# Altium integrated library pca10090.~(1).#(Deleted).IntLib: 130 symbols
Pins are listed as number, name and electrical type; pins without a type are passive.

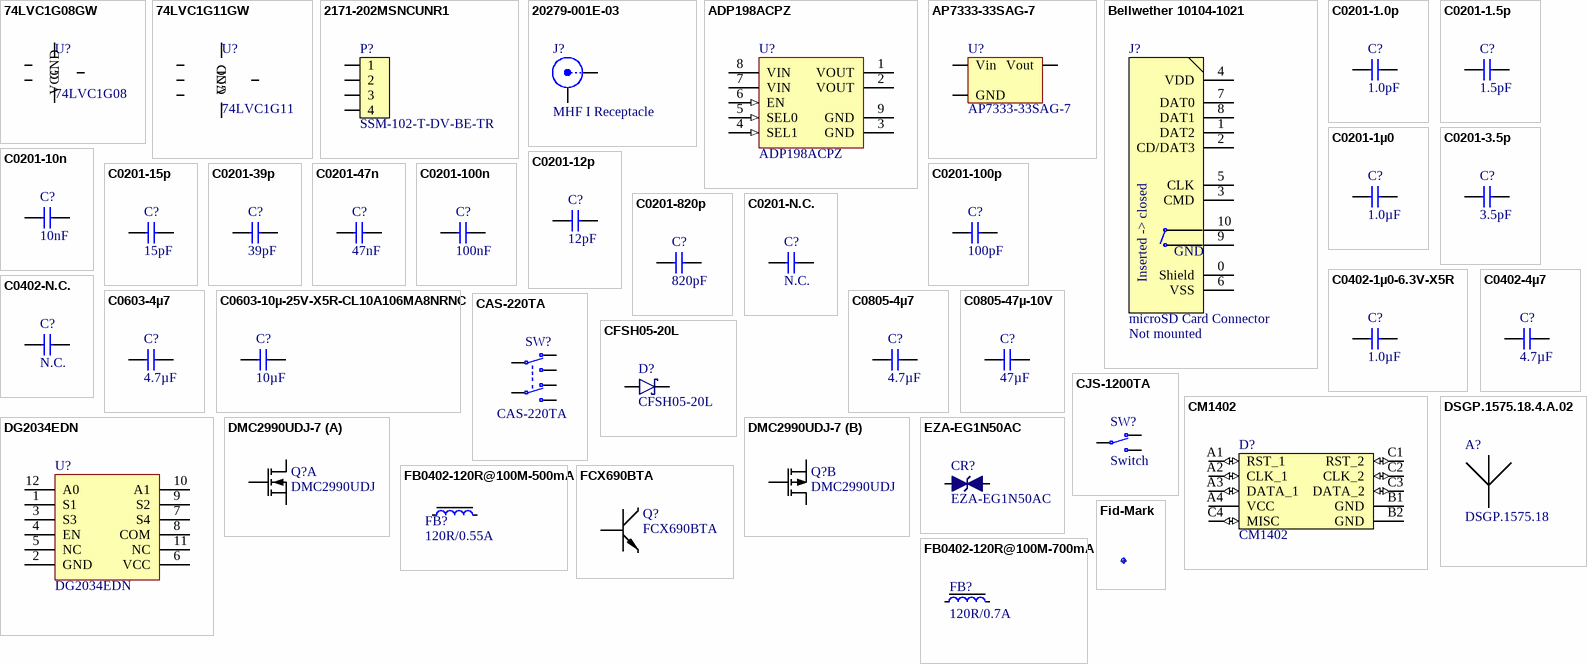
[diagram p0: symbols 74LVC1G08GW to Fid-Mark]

## 74LVC1G08GW
designator U?, comment 74LVC1G08
Single 2-Input AND Gate; Part Number: 74LVC1G08GW; Manufacturer: NXP Semiconductors; Part number IPS: 00000009992; Part number Norautron: N.A.; Artikkelnr Noca: 15049058; Pad Count: 5
footprint SOT65P210X100-5N
pins: 1 A, 2 B, 3 GND (power), 4 Y, 5 VCC (power)

## 74LVC1G11GW
designator U?, comment 74LVC1G11
Single 3-input AND gate; Part Number: 74LVC1G11GW; Manufacturer: NXP Semiconductors; Part number IPS: 00000001430; Part number Norautron: N.A.; Artikkelnr Noca: 15079348; Pad Count: 6
footprint SOT65P210X100-6N
pins: 1 A, 2 GND (power), 3 B, 4 Y, 5 VCC (power), 6 C

## 2171-202MSNCUNR1
designator P?, comment SSM-102-T-DV-BE-TR
.025 SOCKET STRIPS; Part Number: 2171-202MSNCUNR1; Manufacturer: W-CON; Part number IPS: 00000001417; Note: N.A.; Pad Count: 4
footprint SSM-102-T-DV-BE-TR
pins: 1, 2, 3, 4

## 20279-001E-03
designator J?, comment MHF I Receptacle
Ultraminiature Coaxial Connector, 50 Ohm, SMD; Part Number: 20279-001E-03; Manufacturer: Wellshow; Part number IPS: 00000004436; Note: N.A.; Pad Count: 3
footprint COAXIAL RF U.FL-R-SMT-1
pins: 1 X, 2 Y

## ADP198ACPZ
designator U?
Logic Controlled, 1 A, High-Side Load Switch with Reverse Current Blocking; Manufacturer: Analog Devices; Part number IPS: 00000002999; Note: N.A.; Pad Count: 8
footprint UFDFN50P200X200X60_HS-9N
pins: 1 VOUT (power), 2 VOUT (power), 3 GND (power), 4 SEL1 (in), 5 SEL0 (in), 6 EN (in), 7 VIN (power), 8 VIN (power), 9 GND (power)

## AP7333-33SAG-7
designator U?
300mA, Low Quiescent Current, Fast Transient Low Dropout Linear Regulator; Manufacturer: Diodes Incorporated; Part number IPS: 00000001673; Note: N.A.; Artikkelnr Noca: 17039216; Pad Count: 3
footprint SOT-23A
pins: 1 Vin, 2 Vout, 3 GND

## Bellwether 10104-1021
designator J?, comment microSD Card Connector  Assembly: Not mounted
1.10mm Pitch microSD Memory Card Connector, Reverse Mount Surface Mount, Push-Push Type; Part Number: Bellwether 10104-1021; Manufacturer: Bellwether; Manufacturer Part Number: 10104-1021; Note: N.A.; Pad Count: 14
footprint Molex_502774-0891
pins: 0 Shield, 1 DAT2, 2 CD/DAT3, 3 CMD, 4 VDD (power), 5 CLK, 6 VSS (power), 7 DAT0, 8 DAT1, 9, 10

## C0201-1.0p
designator C?, comment 1.0pF
Capacitor, NP0, ±0.05pF, 50V; Part Number: C0201-1.0p; Manufacturer: N.A.; Part number IPS: 00000001247; Pad Count: 2
footprint CAPC0603X03L_C
pins: 1, 2

## C0201-1.5p
designator C?, comment 1.5pF
Capacitor, NP0, ±0.1pF; Part Number: C0201-1.5p; Manufacturer: N.A.; Part number IPS: 00000007107; Note: 50V; Pad Count: 2
footprint CAPC0603X03L_C
pins: 1, 2

## C0201-1µ0
designator C?, comment 1.0µF
Capacitor, X5R, ±10%; Part Number: C0201-1µ0; Manufacturer: N.A.; Part number IPS: 00000001723; Note: 10V; Pad Count: 2
footprint CAPC0603X03L_C
pins: 1, 2

## C0201-3.5p
designator C?, comment 3.5pF
Capacitor, NP0, ±0.1pF, 25V; Part Number: C0201-3.5p; Manufacturer: Murata; Manufacturer Part Number: GJM0335C1H3R5BB01E; Part number IPS: 00000001469; Artikkelnr Noca: N.A.; Pad Count: 2
footprint CAPC0603X03L_C
pins: 1, 2

## C0201-10n
designator C?, comment 10nF
Capacitor, X7R, ±10%; Part Number: C0201-10n; Manufacturer: N.A.; Part number IPS: 00000003480; Note: 10V; Pad Count: 2
footprint CAPC0603X03L_C
pins: 1, 2

## C0201-12p
designator C?, comment 12pF
Capacitor, NP0, ±2%; Part Number: C0201-12p; Manufacturer: N.A.; Part number IPS: 00000007848; Note: 25V; Pad Count: 2
footprint CAPC0603X03L_C
pins: 1, 2

## C0201-15p
designator C?, comment 15pF
Capacitor, NP0, ±5%, 25V; Part Number: C0201-15p; Manufacturer: Murata; Manufacturer Part Number: GRM0335C1E150JD03D; Part number IPS: 00000003193; Artikkelnr Noca: N.A.; Pad Count: 2
footprint CAPC0603X03L_C
pins: 1, 2

## C0201-39p
designator C?, comment 39pF
Capacitor, NP0, ±1%, 25V; Part Number: C0201-39p; Manufacturer: Murata; Manufacturer Part Number: GRM0335C1E390FA01; Part number IPS: 00000001668; Artikkelnr Noca: N.A.; Pad Count: 2
footprint CAPC0603X03L_C
pins: 1, 2

## C0201-47n
designator C?, comment 47nF
Capacitor, X5R, ±10%; Part Number: C0201-47n; Manufacturer: N.A.; Part number IPS: 00000001250; Note: 10V; Pad Count: 2
footprint CAPC0603X03L_C
pins: 1, 2

## C0201-100n
designator C?, comment 100nF
Capacitor, X5R, ±10%; Part Number: C0201-100n; Manufacturer: N.A.; Part number IPS: 00000001248, 00000002505; Note: 16V; Pad Count: 2
footprint CAPC0603X03L_C
pins: 1, 2

## C0201-100p
designator C?, comment 100pF
Capacitor, NP0, ±2%, 25V; Part Number: C0201-100p; Manufacturer: Murata; Manufacturer Part Number: GRM0335C1E101GA01; Part number IPS: 00000007853; Artikkelnr Noca: N.A.; Pad Count: 2
footprint CAPC0603X03L_C
pins: 1, 2

## C0201-820p
designator C?, comment 820pF
Capacitor, X7R, ±10%; Part Number: C0201-820p; Manufacturer: N.A.; Part number IPS: 00000001249; Note: 25V; Pad Count: 2
footprint CAPC0603X03L_C
pins: 1, 2

## C0201-N.C.
designator C?, comment N.C.
Not mounted; Part Number: C0201-N.C.; Manufacturer: N.A.; Note: Chip Cap; Assembly: Not mounted; Pad Count: 2
footprint CAPC0603X03L_C_NC
pins: 1, 2

## C0402-1µ0-6.3V-X5R
designator C?, comment 1.0µF
Capacitor, X5R, ±5%, 6.3V; Part Number: C0402-1µ0-6.3V-X5R; Manufacturer: N.A.; Part number IPS: 00000007786, 00000003457; Artikkelnr Noca: 20039235; Pad Count: 2
footprint CAPC1005X04L
pins: 1, 2

## C0402-4µ7
designator C?, comment 4.7µF
Capacitor, X5R, ±20%; Part Number: C0402-4µ7; Manufacturer: N.A.; Part number IPS: 00000001251, 00000007165; Note: 10V; Artikkelnr Noca: 20039482; Pad Count: 2
footprint CAPC1005X04L
pins: 1, 2

## C0402-N.C.
designator C?, comment N.C.
Not mounted; Part Number: C0402-N.C.; Manufacturer: N.A.; Assembly: Not mounted; Note: Chip Cap; Pad Count: 2
footprint CAPC1005X04L_NC
pins: 1, 2

## C0603-4µ7
designator C?, comment 4.7µF
Capacitor, X5R, ±10%; Part Number: C0603-4µ7; Manufacturer: N.A.; Part number IPS: 00000007783; Note: 6.3V; Artikkelnr Noca: 20069060; Pad Count: 2
footprint CAPC1608X06L
pins: 1, 2

## C0603-10µ-25V-X5R-CL10A106MA8NRNC
designator C?, comment 10µF
Capacitor, X5R, ±20%, 25V; Part Number: C0603-10µ-25V-X5R-CL10A106MA8NRNC; Manufacturer: Samsung Electro-Mechanics America; Manufacturer Part Number: CL10A106MA8NRNC; Part number IPS: 00000009948; Part number Norautron: N.A.; Artikkelnr Noca: 20039436; Pad Count: 2
footprint CAPC1608X06L
pins: 1, 2

## C0805-4µ7
designator C?, comment 4.7µF
Capacitor, X5R, ±10%, 16V; Part Number: C0805-4µ7; Manufacturer: N.A.; Part number IPS: 00000006289; Artikkelnr Noca: 20039266; Pad Count: 2
footprint CAPC2012X11L
pins: 1, 2

## C0805-47µ-10V
designator C?, comment 47µF
Capacitor, X5R, ±20%, 10V; Part Number: C0805-47µ-10V; Manufacturer: Murata; Manufacturer Part Number: GRM21BR61A476ME15; Part number IPS: 00000004759; Artikkelnr Noca: N.A.; Pad Count: 2
footprint CAPC2012X11L
pins: 1, 2

## CAS-220TA
designator SW?
Slide Switch DPDT J Hook; Manufacturer: Copal Electronics Inc; Part number IPS: 00000009983; Note: N.A.; Artikkelnr Noca: 50019042; Pad Count: 6
footprint CAS-220TA
pins: 1 N.O-1, 2 COM-1, 3 N.C-1, 4 N.O-2, 5 COM-2, 6 N.C-2

## CFSH05-20L
designator D?
DIODE SCHOTTKY 20V 500MA SOD882; Manufacturer: Central Semiconductor Corp.; Part number IPS: 00000002493; Note: N.A.; Pad Count: 2
footprint SODFL35X40-2N
pins: 1 A, 3 C

## CJS-1200TA
designator SW?, comment Switch
SMD slide Switch (ON-ON); Part Number: CJS-1200TA; Manufacturer: Copal Electronics Inc; Part number IPS: 00000009982; Note: N.A.; Artikkelnr Noca: 50019068; Pad Count: 3
footprint CJS-120xA
pins: 1 N.C, 2 COM, 3 N.O

## CM1402
designator D?
EMI Network Filter Arrays SIM CARD EMI FILTER WITH ESD PROTECTION; Manufacturer: ON Semiconductor; Manufacturer Part Number: CM1402-03CP; Part number IPS: 00000009949; Note: N.A.; Pad Count: 10
footprint CM1402
pins: A1 RST_1 (io), A2 CLK_1 (io), A3 DATA_1 (io), A4 VCC (power), B1 GND (power), B2 GND (power), C1 RST_2 (io), C2 CLK_2 (io), C3 DATA_2 (io), C4 MISC (io)

## DG2034EDN
designator U?
POWER DOWN FAULT PROTECTED,1.8VT; Manufacturer: Vishay; Manufacturer Part Number: DG2034EDN-T1-GE4; Part number IPS: 00000001429; Note: N.A.; Pad Count: 12
footprint DG2034EDN
pins: 1 S1, 2 GND, 3 S3 (power), 4 EN, 5 NC, 6 VCC (power), 7 S4, 8 COM, 9 S2, 10 A1, 11 NC, 12 A0

## DMC2990UDJ-7
designator Q?, comment DMC2990UDJ
MOSFET, Dual N and P-Channel, 20V, 450mA/310mA, 990mOhm, 350mW; Part Number: DMC2990UDJ-7; Manufacturer: Diodes Incorporated; Part number IPS: 00000004489; Note: N.A.; Pad Count: 6
footprint SOTFL35P100X50-6N
part A pins: 1 S1, 2 G1, 6 D1
part B pins: 3 D2, 4 S2, 5 G2

## DSGP.1575.18.4.A.02
designator A?, comment DSGP.1575.18
18 x 18 mm Low Profile GPS L1 / GALILEO E1 Passive Patch Antenna; Part Number: DSGP.1575.18.4.A.02; Manufacturer: Taoglas; Part number IPS: 00000004435; Note: N.A.; Pad Count: 2
footprint DSGP.1575.18
pins: 1, 2 GND (power) hidden to GND

## EZA-EG1N50AC
designator CR?
ESD Suppressor, 30V, 0.04pF; Manufacturer: Panasonic; Part number IPS: 00000004437; Note: N.A.; Pad Count: 2
footprint RESC0603X03L_C
pins: 1, 2

## FB0402-120R@100M-500mA
designator FB?, comment 120R/0.55A
Ferrite Bead, 120 Ohm @ 100MHz, 500mA, 250 mOhm Max; Part Number: FB0402-120R@100M-500mA; Manufacturer: Murata; Manufacturer Part Number: BLM15AG121SN1D; Part number IPS: 00000009954; Part number Norautron: N.A.; Note: Chip EMIFIL Inductor Type Chip Ferrite Bead; Artikkelnr Noca: 33029317; Pad Count: 2
footprint INDC1005X04L
pins: 1, 2

## FB0402-120R@100M-700mA
designator FB?, comment 120R/0.7A
Ferrite Bead, 120 Ohm @ 100MHz, 700mA, 130 mOhm Max; Part Number: FB0402-120R@100M-700mA; Manufacturer: Murata; Manufacturer Part Number: BLM15AX121SN1; Part number IPS: 00000004487; Note: N.A.; Pad Count: 2
footprint INDC1005X04L
pins: 1, 2

## FCX690BTA
designator Q?
45V NPN high gain power transistor; Manufacturer: Diodes Incorporated; Part number IPS: 00000009974; Note: N.A.; Artikkelnr Noca: 35010019; Pad Count: 3
footprint SOT89-150P409X160-3N
pins: 1 B, 2 C (power), 3 E (power)

## Fid-Mark
designator Fid?, comment Fiducial mark  (value not drawn)
Part Number: Fid-Mark; Manufacturer: N.A.; Value: N.A.; Pad Count: 1
footprint Fiducial

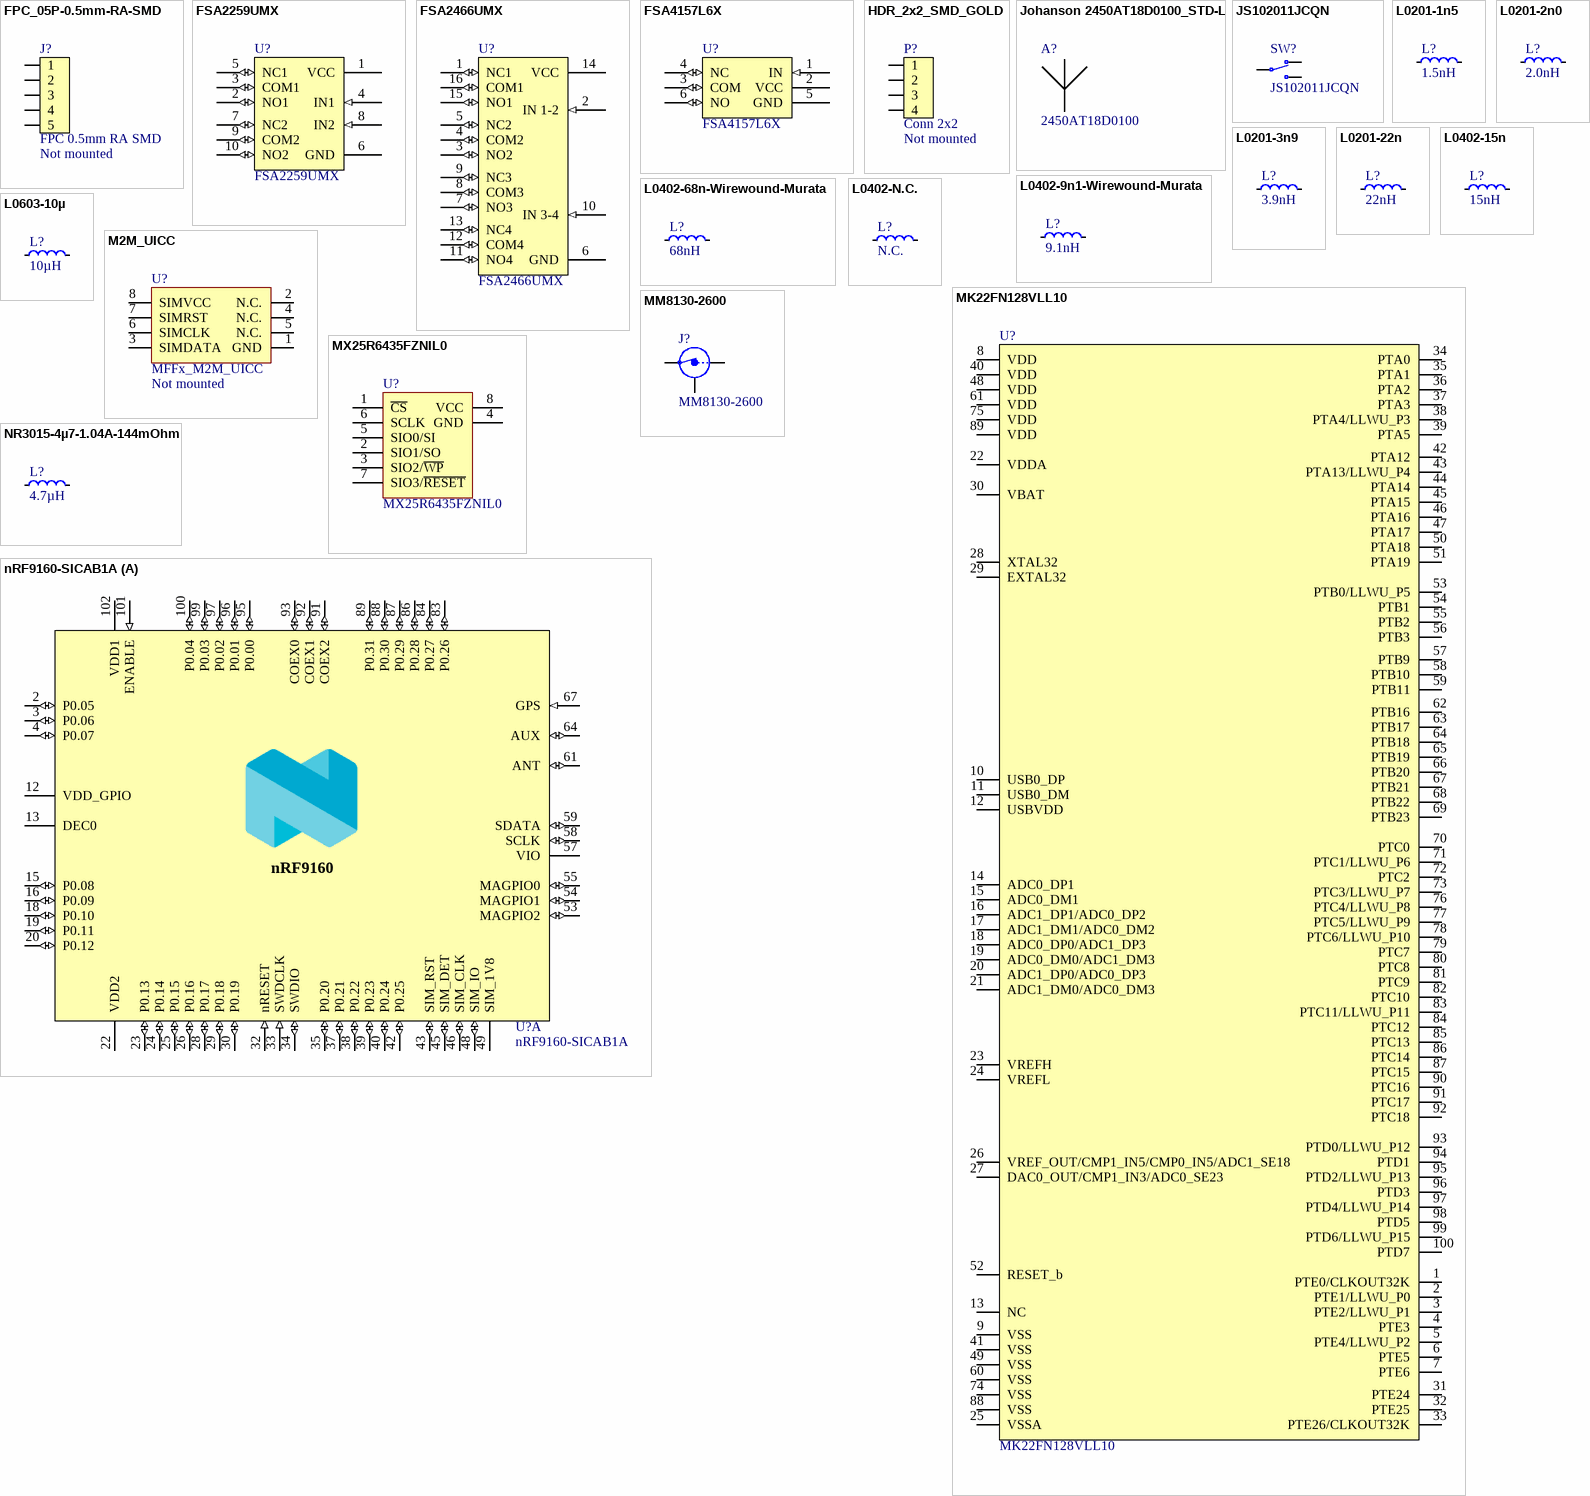
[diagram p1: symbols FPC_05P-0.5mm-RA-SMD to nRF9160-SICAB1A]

## FPC_05P-0.5mm-RA-SMD
designator J?, comment FPC 0.5mm RA SMD  Assembly: Not mounted
0.5mm FPC, 5P,Right Angle SMT,Double Contact,H=1.2mm,White, Tin plated; Part Number: FPC_05P-0.5mm-RA-SMD; Manufacturer: W-CON; Manufacturer Part Number: 5141-05RZDNWR02; Part number IPS: 00000007792; Note: N.A.; Artikkelnr Noca: 55010020; Pad Count: 7
footprint FPC_05P-0.5mm-RA-SMD
pins: 1, 2, 3, 4, 5

## FSA2259UMX
designator U?
Low-Voltage, Dual-SPDT analog Switch; Manufacturer: ON Semiconductor; Part number IPS: 00000002998; Note: N.A.; Pad Count: 10
footprint UFQFN40P140X180X55-10N
pins: 1 VCC (power), 2 NO1 (io), 3 COM1 (io), 4 IN1 (in), 5 NC1 (io), 6 GND (power), 7 NC2 (io), 8 IN2 (in), 9 COM2 (io), 10 NO2 (io)

## FSA2466UMX
designator U?
Data / Audio Low-Voltage Dual DPDT Analog Switch; Manufacturer: ON Semiconductor; Part number IPS: 00000009986; Note: N.A.; Artikkelnr Noca: 15070069; Pad Count: 16
footprint XQFN40P180X260X50-16N
pins: 1 NC1 (io), 2 IN 1-2 (in), 3 NO2 (io), 4 COM2 (io), 5 NC2 (io), 6 GND (power), 7 NO3 (io), 8 COM3 (io), 9 NC3 (io), 10 IN 3-4 (in), 11 NO4 (io), 12 COM4 (io), 13 NC4 (io), 14 VCC (power), 15 NO1 (io), 16 COM1 (io)
1 alternate drawing of the same symbol

## FSA4157L6X
designator U?
Low-Voltage, SPDT Analog Switch, 1.65 V to 5.5 V; Manufacturer: ON Semiconductor; Part number IPS: 00000003748; Note: N.A.; Pad Count: 6
footprint PSON50P100X60-6N
pins: 1 IN (in), 2 VCC (power), 3 COM (io), 4 NC (io), 5 GND (power), 6 NO (io)

## HDR_2x2_SMD_GOLD
designator P?, comment Conn 2x2  Assembly: Not mounted
CONN HEADER 4POS .100" VERT 15AU; Part Number: HDR_2x2_SMD_GOLD; Manufacturer: Molex; Note: SMD, gold plating; Artikkelnr Noca: N.A.; Pad Count: 4
footprint HDR_2x2-SMD
pins: 1, 2, 3, 4

## Johanson 2450AT18D0100_STD-L
designator A?, comment 2450AT18D0100
2.45 GHz chip antenna; Part Number: Johanson 2450AT18D0100_STD-L; Manufacturer: Johanson Technology; Part number IPS: 00000001415; Note: N.A.; Artikkelnr Noca: 53059035; Pad Count: 4
footprint 2450AT18D0100_STD-L
pins: 1, 2 GND (power) hidden to GND

## JS102011JCQN
designator SW?
Sub-Miniature Slide Switch, SPDT, 300mA, 6V, Vertical, SMD; Manufacturer: C&K; Part number IPS: 00000009980; Note: N.A.; Pad Count: 3
footprint JS102011JCQN
pins: 1 N.C, 2 COM, 3 N.O

## L0201-1n5
designator L?, comment 1.5nH
Inductor, 650mA, ±0.1nH; Part Number: L0201-1n5; Manufacturer: Murata; Manufacturer Part Number: LQP03TQ1N5B02D; Part number IPS: 00000000836; Note: N.A.; Pad Count: 2
footprint INDC0603X03L_C
pins: 1, 2

## L0201-2n0
designator L?, comment 2.0nH
Chip Inductor; Part Number: L0201-2n0; Manufacturer: Murata; Manufacturer Part Number: LQP03TN2N0B02D; Part number IPS: 00000001670; Note: High frequency chip inductor ±5%; Artikkelnr Noca: N.A.; Pad Count: 2
footprint INDC0603X03L_C
pins: 1, 2

## L0201-3n9
designator L?, comment 3.9nH
Inductor, 400mA, ±0.1nH; Part Number: L0201-3n9; Manufacturer: Murata; Manufacturer Part Number: LQP03TN3N9B02D; Part number IPS: 00000001253; Note: N.A.; Pad Count: 2
footprint INDC0603X03L_C
pins: 1, 2

## L0201-22n
designator L?, comment 22nH
Chip Inductor; Part Number: L0201-22n; Manufacturer: N.A.; Part number IPS: 00000001478; Note: High frequency chip inductor ±10%; Pad Count: 2
footprint INDC0603X03L_C
pins: 1, 2

## L0402-9n1-Wirewound-Murata
designator L?, comment 9.1nH
Inductor, 540mA, ±2%, 140mΩ, Q=25; Part Number: L0402-9n1-Wirewound-Murata; Manufacturer: Murata; Manufacturer Part Number: LQW15AN9N1G00; Part number IPS: 00000002497; Note: -55°C ~ 125°C; Artikkelnr Noca: N.A.; Pad Count: 2
footprint INDC1005X04L_WW
pins: 1, 2

## L0402-15n
designator L?, comment 15nH
Inductor, 320mA, ±5%; Part Number: L0402-15n; Manufacturer: Taiyo Yuden; Manufacturer Part Number: HK100515NJ-T; Part number IPS: 00000001262; Part number Norautron: N.A.; Note: High frequency chip inductor ±10%; Artikkelnr Noca: 33029323; Pad Count: 2
footprint INDC1005X04L
pins: 1, 2

## L0402-68n-Wirewound-Murata
designator L?, comment 68nH
Inductor, 140mA, ±2%, 1960mΩ, Q=20; Part Number: L0402-68n-Wirewound-Murata; Manufacturer: Murata; Manufacturer Part Number: LQW15AN68NG00; Part number IPS: 00000002494; Note: -55°C ~ 125°C; Artikkelnr Noca: N.A.; Pad Count: 2
footprint INDC1005X04L_WW
pins: 1, 2

## L0402-N.C.
designator L?, comment N.C.
Not mounted; Part Number: L0402-N.C.; Manufacturer: N.A.; Assembly: Not mounted; Pad Count: 2
footprint INDC1005X04L_NC
pins: 1, 2

## L0603-10µ
designator L?, comment 10µH
Inductor, 80mA, ±10%; Part Number: L0603-10µ; Manufacturer: Taiyo Yuden; Manufacturer Part Number: LBMF1608T100K; Part number IPS: 00000007794; Part number Norautron: N.A.; Note: LBMF1608T100K 10µH 80mA 0603; Artikkelnr Noca: 33029314; Pad Count: 2
footprint INDC1608X06L
pins: 1, 2

## M2M_UICC
designator U?, comment MFFx_M2M_UICC  Assembly: Not mounted
M2M UICC SIM Card; Manufacturer: N.A.; Pad Count: 8
footprint SON127P600X90_HS-8N
pins: 1 GND, 2 N.C., 3 SIMDATA, 4 N.C., 5 N.C., 6 SIMCLK, 7 SIMRST, 8 SIMVCC

## MK22FN128VLL10
designator U?
100MHz Cortex-M4F Performance MCU, 128kB Flash, 24kB SRAM, Full-Speed USB; Manufacturer: NXP Semiconductors; Part number IPS: 00000001366; Note: N.A.; Pad Count: 100
footprint TSQFP50P1600X1600X160-100N
pins: 1 PTE0/CLKOUT32K, 2 PTE1/LLWU_P0, 3 PTE2/LLWU_P1, 4 PTE3, 5 PTE4/LLWU_P2, 6 PTE5, 7 PTE6, 8 VDD, 9 VSS, 10 USB0_DP, 11 USB0_DM, 12 USBVDD, 13 NC, 14 ADC0_DP1, 15 ADC0_DM1, 16 ADC1_DP1/ADC0_DP2, 17 ADC1_DM1/ADC0_DM2, 18 ADC0_DP0/ADC1_DP3, 19 ADC0_DM0/ADC1_DM3, 20 ADC1_DP0/ADC0_DP3, 21 ADC1_DM0/ADC0_DM3, 22 VDDA, 23 VREFH, 24 VREFL, 25 VSSA, 26 VREF_OUT/CMP1_IN5/CMP0_IN5/ADC1_SE18, 27 DAC0_OUT/CMP1_IN3/ADC0_SE23, 28 XTAL32, 29 EXTAL32, 30 VBAT, 31 PTE24, 32 PTE25, 33 PTE26/CLKOUT32K, 34 PTA0, 35 PTA1, 36 PTA2, 37 PTA3, 38 PTA4/LLWU_P3, 39 PTA5, 40 VDD, 41 VSS, 42 PTA12, 43 PTA13/LLWU_P4, 44 PTA14, 45 PTA15, 46 PTA16, 47 PTA17, 48 VDD, 49 VSS, 50 PTA18, 51 PTA19, 52 RESET_b, 53 PTB0/LLWU_P5, 54 PTB1, 55 PTB2, 56 PTB3, 57 PTB9, 58 PTB10, 59 PTB11, 60 VSS, 61 VDD, 62 PTB16, 63 PTB17, 64 PTB18, 65 PTB19, 66 PTB20, 67 PTB21, 68 PTB22, 69 PTB23, 70 PTC0, 71 PTC1/LLWU_P6, 72 PTC2, 73 PTC3/LLWU_P7, 74 VSS, 75 VDD, 76 PTC4/LLWU_P8, 77 PTC5/LLWU_P9, 78 PTC6/LLWU_P10, 79 PTC7, 80 PTC8, 81 PTC9, 82 PTC10, 83 PTC11/LLWU_P11, 84 PTC12, 85 PTC13, 86 PTC14, 87 PTC15, 88 VSS, 89 VDD, 90 PTC16, 91 PTC17, 92 PTC18, 93 PTD0/LLWU_P12, 94 PTD1, 95 PTD2/LLWU_P13, 96 PTD3, 97 PTD4/LLWU_P14, 98 PTD5, 99 PTD6/LLWU_P15, 100 PTD7

## MM8130-2600
designator J?
Coaxial Connector with Switch; Manufacturer: Murata; Part number IPS: 00000009955; Note: N.A.; Artikkelnr Noca: 55029011; Pad Count: 3
footprint COAXIAL-SWF
pins: 1 IN, 2 Shield, 3 OUT

## MX25R6435FZNIL0
designator U?
Ultra low power, 64M-bit, serial multi I/O flash memory; Manufacturer: Macronix; Part number IPS: 00000004370; Note: N.A.; Artikkelnr Noca: 15020015; Pad Count: 8
footprint SON127P600X80_HS-9N
pins: 1 ~{CS}, 2 SIO1/SO, 3 SIO2/~{WP}, 4 GND, 5 SIO0/SI, 6 SCLK, 7 SIO3/~{RESET}, 8 VCC, 9 GND hidden to GND

## NR3015-4µ7-1.04A-144mOhm
designator L?, comment 4.7µH
Ferrite Inductor, Shielded, 1,04A, 144mOhm; Part Number: NR3015-4µ7-1.04A-144mOhm; Manufacturer: Taiyo Yuden; Manufacturer Part Number: NR3015T4R7M; Part number IPS: 00000009960; Note: N.A.; Artikkelnr Noca: 33029551; Pad Count: 2
footprint TY-NR3015
pins: 1, 2

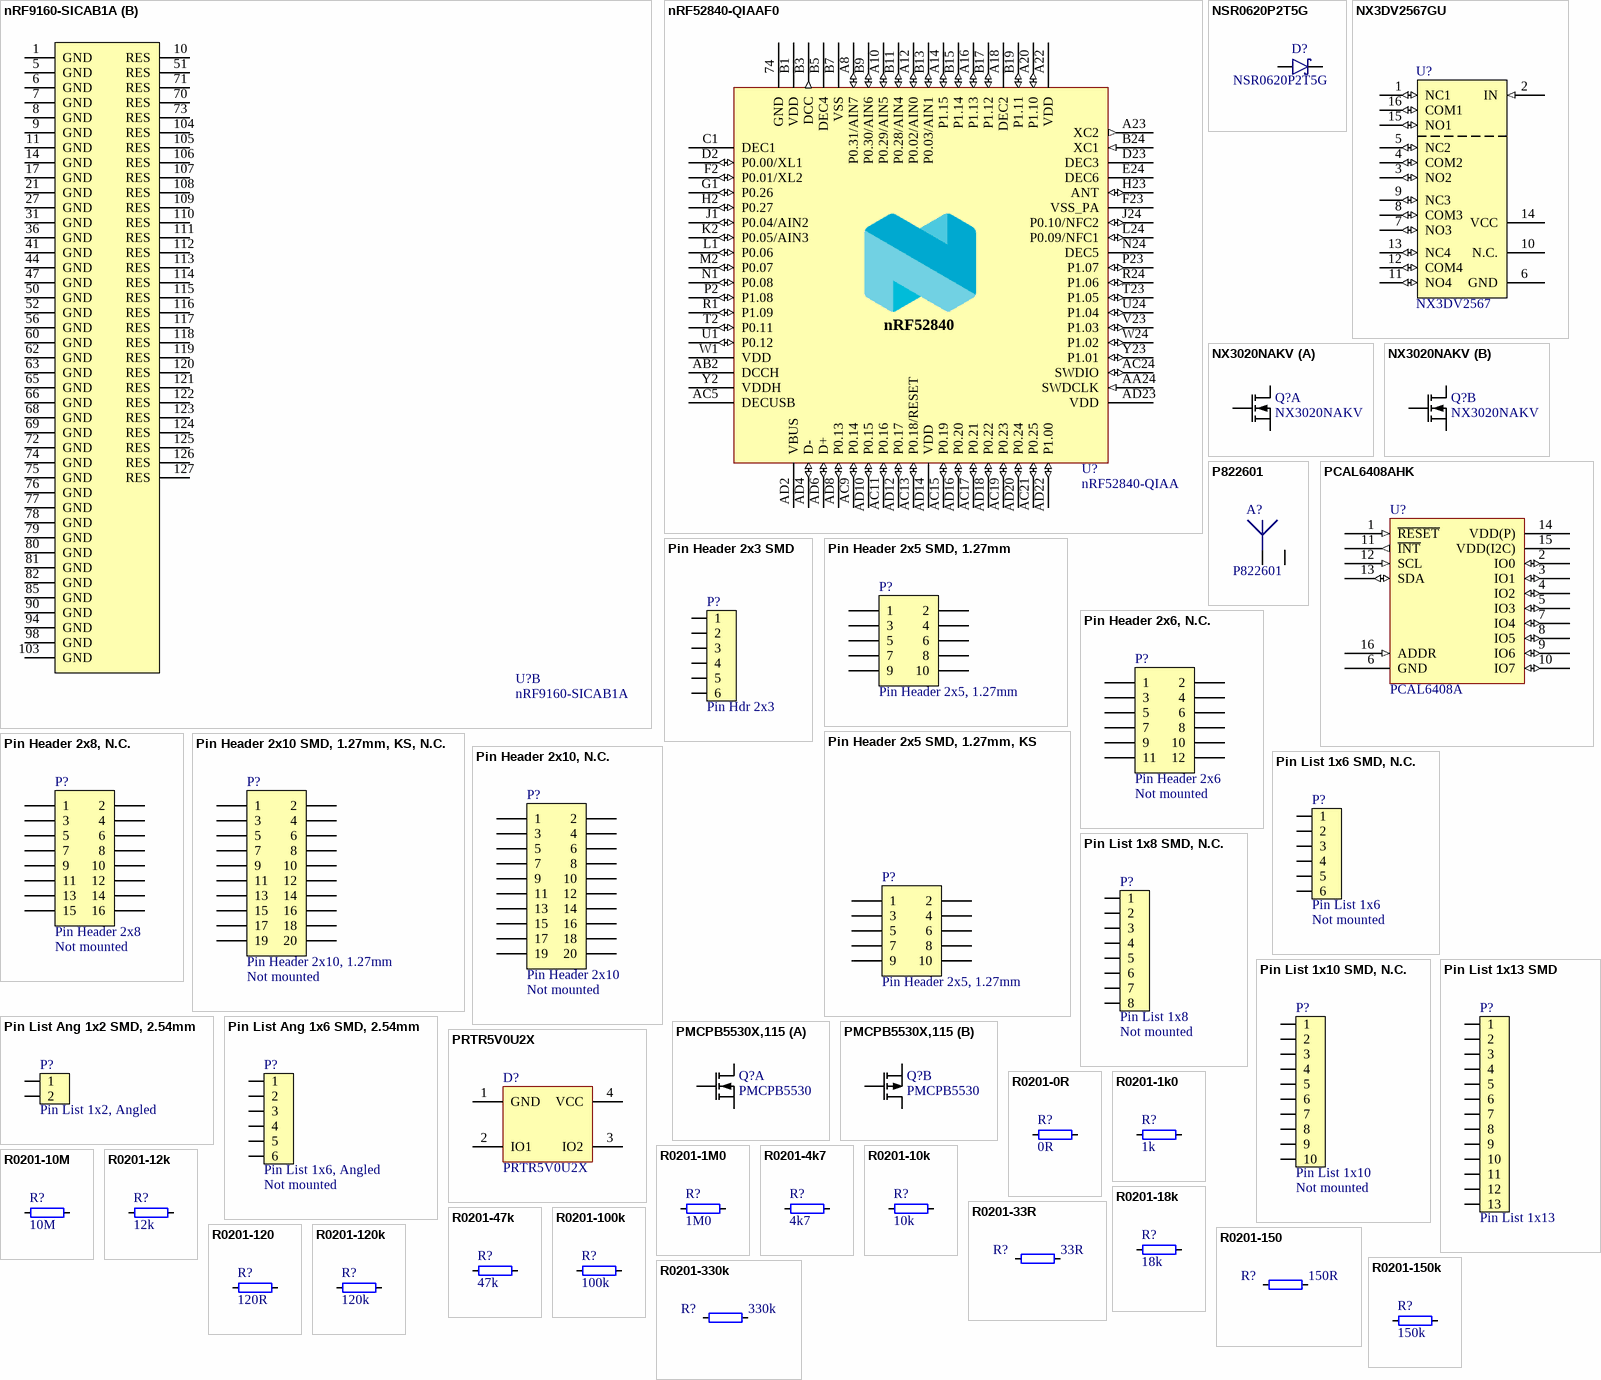
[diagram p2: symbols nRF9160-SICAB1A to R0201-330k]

## nRF9160-SICAB1A
designator U?
Low power System-in-Package with integrated LTE-M/NB-IoT modem and GPS; Manufacturer: Nordic Semiconductor; Part number IPS: 80000002329; Note: N.A.; Pad Count: 161
footprint LGA50P1600X1050X104-161N
part A pins: 2 P0.05 (io), 3 P0.06 (io), 4 P0.07 (io), 12 VDD_GPIO (power), 13 DEC0 (power), 15 P0.08 (io), 16 P0.09 (io), 18 P0.10 (io), 19 P0.11 (io), 20 P0.12 (io), 22 VDD2 (power), 23 P0.13 (io), 24 P0.14 (io), 25 P0.15 (io), 26 P0.16 (io), 28 P0.17 (io), 29 P0.18 (io), 30 P0.19 (io), 32 nRESET (in), 33 SWDCLK (in), 34 SWDIO (io), 35 P0.20 (io), 37 P0.21 (io), 38 P0.22 (io), 39 P0.23 (io), 40 P0.24 (io), 42 P0.25 (io), 43 SIM_RST (io), 45 SIM_DET (io), 46 SIM_CLK (io), 48 SIM_IO (io), 49 SIM_1V8 (power), 53 MAGPIO2 (io), 54 MAGPIO1 (io), 55 MAGPIO0 (io), 57 VIO (power), 58 SCLK (io), 59 SDATA (io), 61 ANT (io), 64 AUX (io), 67 GPS (in), 83 P0.26 (io), 84 P0.27 (io), 86 P0.28 (io), 87 P0.29 (io), 88 P0.30 (io), 89 P0.31 (io), 91 COEX2 (io), 92 COEX1 (io), 93 COEX0 (io), 95 P0.00 (io), 96 P0.01 (io), 97 P0.02 (io), 99 P0.03 (io), 100 P0.04 (io), 101 ENABLE (in), 102 VDD1 (power)
part B pins: 1 GND (power), 5 GND (power), 6 GND, 7 GND, 8 GND, 9 GND (power), 10 RES, 11 GND, 14 GND (power), 17 GND (power), 21 GND (power), 27 GND (power), 31 GND (power), 36 GND (power), 41 GND (power), 44 GND (power), 47 GND (power), 50 GND (power), 51 RES, 52 GND (power), 56 GND (power), 60 GND (power), 62 GND (power), 63 GND (power), 65 GND (power), 66 GND (power), 68 GND, 69 GND, 70 RES, 71 RES, 72 GND (power), 73 RES, 74 GND (power), 75 GND (power), 76 GND (power), 77 GND (power), 78 GND (power), 79 GND (power), 80 GND (power), 81 GND (power), 82 GND (power), 85 GND (power), 90 GND (power), 94 GND (power), 98 GND (power), 103 GND (power), 104 RES, 105 RES, 106 RES, 107 RES, 108 RES, 109 RES, 110 RES, 111 RES, 112 RES, 113 RES, 114 RES, 115 RES, 116 RES, 117 RES, 118 RES, 119 RES, 120 RES, 121 RES, 122 RES, 123 RES, 124 RES, 125 RES, 126 RES, 127 RES

## nRF52840-QIAAF0
designator U?, comment nRF52840-QIAA
Multi-protocol Bluetooth Low Energy, IEEE 802.15.4, ANT and 2.4GHz proprietary system-on-chip; Part Number: nRF52840-QIAAF0; Manufacturer: Nordic Semiconductor; Part number IPS: 80000002377; Note: N.A.; Pad Count: 73
footprint AQFN50P700X700X85_HS-74N
pins: 74 GND (power), A8 P0.31/AIN7 (io), A10 P0.29/AIN5 (io), A12 P0.02/AIN0 (io), A14 P1.15 (io), A16 P1.13 (io), A18 DEC2 (power), A20 P1.10 (io), A22 VDD (power), A23 XC2 (out), AA24 SWDCLK (in), AB2 DCCH (power), AC5 DECUSB (power), AC9 P0.14 (io), AC11 P0.16 (io), AC13 P0.18/RESET (io), AC15 P0.19 (io), AC17 P0.21 (io), AC19 P0.23 (io), AC21 P0.25 (io), AC24 SWDIO (io), AD2 VBUS (power), AD4 D- (io), AD6 D+ (io), AD8 P0.13 (io), AD10 P0.15 (io), AD12 P0.17 (io), AD14 VDD (power), AD16 P0.20 (io), AD18 P0.22 (io), AD20 P0.24 (io), AD22 P1.00 (io), AD23 VDD (power), B1 VDD (power), B3 DCC (out), B5 DEC4 (power), B7 VSS (power), B9 P0.30/AIN6 (io), B11 P0.28/AIN4 (io), B13 P0.03/AIN1 (io), B15 P1.14 (io), B17 P1.12 (io), B19 P1.11 (io), B24 XC1 (in), C1 DEC1 (power), D2 P0.00/XL1 (io), D23 DEC3 (power), E24 DEC6 (power), F2 P0.01/XL2 (io), F23 VSS_PA (power), G1 P0.26 (io), H2 P0.27 (io), H23 ANT (io), J1 P0.04/AIN2 (io), J24 P0.10/NFC2 (io), K2 P0.05/AIN3 (io), L1 P0.06 (io), L24 P0.09/NFC1 (io), M2 P0.07 (io), N1 P0.08 (io), N24 DEC5 (power), P2 P1.08 (io), P23 P1.07 (io), R1 P1.09 (io), R24 P1.06 (io), T2 P0.11 (io), T23 P1.05 (io), U1 P0.12 (io), U24 P1.04 (io), V23 P1.03 (io), W1 VDD (power), W24 P1.02 (io), Y2 VDDH (power), Y23 P1.01 (io)

## NSR0620P2T5G
designator D?
20V schottky barrier diode, Vf 350 mV @ 100 mA, Ir 2.0 µA @ 10 V, If 500 mA; Manufacturer: ON Semiconductor; Part number IPS: 00000009952; Note: N.A.; Artikkelnr Noca: 10029169; Pad Count: 2
footprint SODFL100X40-2N
pins: 1 C, 2 A

## NX3DV2567GU
designator U?, comment NX3DV2567
Low-ohmic four-pole double-throw analog switch; Part Number: NX3DV2567GU; Manufacturer: NXP Semiconductors; Part number IPS: 00000007816; Note: N.A.; Artikkelnr Noca: 15079317; Pad Count: 16
footprint XQFN40P180X260X50-16N
pins: 1 NC1 (io), 2 IN (in), 3 NO2 (io), 4 COM2 (io), 5 NC2 (io), 6 GND (power), 7 NO3 (io), 8 COM3 (io), 9 NC3 (io), 10 N.C., 11 NO4 (io), 12 COM4 (io), 13 NC4 (io), 14 VCC (power), 15 NO1 (io), 16 COM1 (io)
2 alternate drawings of the same symbol

## NX3020NAKV
designator Q?
MOSFET 2N-CH 30V 0.2A SOT666; Manufacturer: Nexperia; Manufacturer Part Number: NX3020NAKV,115; Part number IPS: 00000001724; Note: N.A.; Pad Count: 6
footprint NX3020NAKV
part A pins: 1 S1, 2 G1, 6 D1
part B pins: 3 D2, 4 S2, 5 G2

## P822601
designator A?
ANTENNA PRESTTA OCTABAND LTE; Manufacturer: Ethertronics; Part number IPS: 00000009001; Note: N.A.; Pad Count: 2
footprint P822601
pins: 1, 2

## PCAL6408AHK
designator U?, comment PCAL6408A
8-bit I2C-bus I/O expander with interrupt output; Part Number: PCAL6408AHK; Manufacturer: NXP Semiconductors; Part number IPS: 00000009987; Note: N.A.; Artikkelnr Noca: 15079321; Pad Count: 16
footprint XQFN40P180X260X50-16N
pins: 1 ~{RESET} (in), 2 IO0 (io), 3 IO1 (io), 4 IO2 (io), 5 IO3 (io), 6 GND (power), 7 IO4 (io), 8 IO5 (io), 9 IO6 (io), 10 IO7 (io), 11 ~{INT} (out), 12 SCL (in), 13 SDA (io), 14 VDD(P) (power) "VDD 2.3V - 5.5V", 15 VDD(I2C) (power), 16 ADDR (in)

## Pin Header 2x3 SMD
designator P?, comment Pin Hdr 2x3
Pin Header 2x3, 2.54mm (100mil) SMD; Part Number: Pin Header 2x3 SMD; Manufacturer: W-CON; Manufacturer Part Number: 1125-1203S0M116R1; Part number IPS: 00000009966; Part number Norautron: N.A.; Artikkelnr Noca: 55010007; Pad Count: 6
footprint HDR_2x3-SMD
pins: 1, 2, 3, 4, 5, 6

## Pin Header 2x5 SMD, 1.27mm
designator P?, comment Pin Header 2x5, 1.27mm
Pin Header 2x5, 1.27mm (50mil), SMD; Part Number: Pin Header 2x5 SMD, 1.27mm; Manufacturer: W-CON; Manufacturer Part Number: 1325-1205S0M078R1; Part number IPS: 00000009970; Note: N.A.; Artikkelnr Noca: 55019196; Pad Count: 10
footprint HDR_2x5-SMD-1.27mm
pins: 1, 2, 3, 4, 5, 6, 7, 8, 9, 10

## Pin Header 2x5 SMD, 1.27mm, KS
designator P?, comment Pin Header 2x5, 1.27mm
Pin Header 2x5, 1.27mm (50mil), SMD, Keying Shroud; Part Number: Pin Header 2x5 SMD, 1.27mm, KS; Manufacturer: W-CON; Manufacturer Part Number: 3132-10MS0BK00R1; Part number IPS: 00000009968; Note: N.A.; Artikkelnr Noca: 55010009; Pad Count: 10
footprint HDR_2x5-SMD-1.27mm-K
pins: 1, 2, 3, 4, 5, 6, 7, 8, 9, 10

## Pin Header 2x6, N.C.
designator P?, comment Pin Header 2x6  Assembly: Not mounted
Pin Header 2x6, 2.54mm (100mil); Part Number: Pin Header 2x6, N.C.; Manufacturer: N.A.; Pad Count: 12
footprint HDR_2x6-NC
pins: 1, 2, 3, 4, 5, 6, 7, 8, 9, 10, 11, 12

## Pin Header 2x8, N.C.
designator P?, comment Pin Header 2x8  Assembly: Not mounted
Pin Header 2x8, 2.54mm (100mil); Part Number: Pin Header 2x8, N.C.; Manufacturer: N.A.; Pad Count: 16
footprint HDR_2x8-NC
pins: 1, 2, 3, 4, 5, 6, 7, 8, 9, 10, 11, 12, 13, 14, 15, 16
1 alternate drawing of the same symbol

## Pin Header 2x10 SMD, 1.27mm, KS, N.C.
designator P?, comment Pin Header 2x10, 1.27mm  Assembly: Not mounted
Pin Header 2x10, 1.27mm (50mil), SMD, Keying Shroud; Part Number: Pin Header 2x10 SMD, 1.27mm, KS, N.C.; Manufacturer: W-CON; Manufacturer Part Number: 3132-20MS0BK00R1; Note: N.A.; Pad Count: 20
footprint HDR_2x10-SMD-1.27mm-NC
pins: 1, 2, 3, 4, 5, 6, 7, 8, 9, 10, 11, 12, 13, 14, 15, 16, 17, 18, 19, 20

## Pin Header 2x10, N.C.
designator P?, comment Pin Header 2x10  Assembly: Not mounted
Pin Header 2x10, 2.54mm (100mil); Part Number: Pin Header 2x10, N.C.; Manufacturer: N.A.; Pad Count: 20
footprint HDR_2x10-NC
pins: 1, 2, 3, 4, 5, 6, 7, 8, 9, 10, 11, 12, 13, 14, 15, 16, 17, 18, 19, 20

## Pin List 1x6 SMD, N.C.
designator P?, comment Pin List 1x6  Assembly: Not mounted
Pin List 1x6, 2.54mm (100mil), SMD; Part Number: Pin List 1x6 SMD, N.C.; Manufacturer: W-CON; Manufacturer Part Number: 1125-1106S0M116R2; Note: N.A.; Artikkelnr Noca: 55010026; Pad Count: 6
footprint LIST_1x6_SMD-NC
pins: 1, 2, 3, 4, 5, 6

## Pin List 1x8 SMD, N.C.
designator P?, comment Pin List 1x8  Assembly: Not mounted
Pin List 1x8, 2.54mm (100mil), SMD; Part Number: Pin List 1x8 SMD, N.C.; Manufacturer: W-CON; Manufacturer Part Number: 1125-1108S0M116R2; Note: N.A.; Artikkelnr Noca: 55010006; Pad Count: 8
footprint LIST_1x8_SMD-NC
pins: 1, 2, 3, 4, 5, 6, 7, 8

## Pin List 1x10 SMD, N.C.
designator P?, comment Pin List 1x10  Assembly: Not mounted
Pin List 1x10, 2.54mm (100mil), SMD; Part Number: Pin List 1x10 SMD, N.C.; Manufacturer: W-CON; Manufacturer Part Number: 1125-1110S0M116R2; Note: N.A.; Artikkelnr Noca: 55010028; Pad Count: 10
footprint LIST_1x10_SMD-NC
pins: 1, 2, 3, 4, 5, 6, 7, 8, 9, 10

## Pin List 1x13 SMD
designator P?, comment Pin List 1x13
Pin List 1x13, 2.54mm (100mil), SMD; Part Number: Pin List 1x13 SMD; Manufacturer: N.A.; Part number IPS: 00000002499; Pad Count: 13
footprint LIST_1x13_SMD
pins: 1, 2, 3, 4, 5, 6, 7, 8, 9, 10, 11, 12, 13

## Pin List Ang 1x2 SMD, 2.54mm
designator P?, comment Pin List 1x2, Angled
Pin List 1x2, 2.54mm (100mil), Right Angled, SMD; Part Number: Pin List Ang 1x2 SMD, 2.54mm; Manufacturer: W-CON; Manufacturer Part Number: 1125B-1102S0Z135R2; Part number IPS: 00000009972; Note: N.A.; Artikkelnr Noca: 55010023; Pad Count: 2
footprint LIST_ANG_1x2-SMD-2.54MM
pins: 1, 2

## Pin List Ang 1x6 SMD, 2.54mm
designator P?, comment Pin List 1x6, Angled  Assembly: Not mounted
Pin List 1x6, 2.54mm (100mil), Right Angled, SMD; Part Number: Pin List Ang 1x6 SMD, 2.54mm; Manufacturer: N.A.; Part number IPS: 00000003922; Pad Count: 6
footprint LIST_ANG_1x6-SMD-2.54MM
pins: 1, 2, 3, 4, 5, 6

## PMCPB5530X,115
designator Q?, comment PMCPB5530
Mosfet Array N and P-Channel 20V 4A (Ta), 3.4A (Ta) 490mW Surface Mount 6-HUSON-EP (2x2); Part Number: PMCPB5530X,115; Manufacturer: Nexperia; Part number IPS: 00000001918; Note: N.A.; Pad Count: 8
footprint PMCPB5530X
part A pins: 1 S1, 2 G1, 6 D1
part B pins: 3 D2, 4 S2, 5 G2

## PRTR5V0U2X
designator D?
Ultra low capacitance double rail-to-rail ESD protection diode; Manufacturer: NXP Semiconductors; Part number IPS: 00000009951; Note: N.A.; Artikkelnr Noca: 10069015; Pad Count: 4
footprint SOT190P230X110-4L
pins: 1 GND, 2 IO1, 3 IO2, 4 VCC

## R0201-0R
designator R?, comment 0R
Resistor, ±5%, 0.05W; Part Number: R0201-0R; Manufacturer: N.A.; Part number IPS: 00000003245; Note: Chip Res 5%; Pad Count: 2
footprint RESC0603X03L_C
pins: 1, 2

## R0201-1k0
designator R?, comment 1k
Resistor, ±1%, 0.05W; Part Number: R0201-1k0; Manufacturer: N.A.; Part number IPS: 00000005786; Note: Chip Res 1%; Pad Count: 2
footprint RESC0603X03L_C
pins: 1, 2

## R0201-1M0
designator R?, comment 1M0
Resistor, ±1%, 0.05W; Part Number: R0201-1M0; Manufacturer: N.A.; Part number IPS: 00000001418; Note: Chip Res 1%; Pad Count: 2
footprint RESC0603X03L_C
pins: 1, 2

## R0201-4k7
designator R?, comment 4k7
Resistor, ±1%, 0.05W; Part Number: R0201-4k7; Manufacturer: N.A.; Part number IPS: 00000001706; Note: Chip Res 1%; Pad Count: 2
footprint RESC0603X03L_C
pins: 1, 2

## R0201-10k
designator R?, comment 10k
Resistor, ±1%, 0.05W; Part Number: R0201-10k; Manufacturer: N.A.; Part number IPS: 00000001255; Note: Chip Res 1%; Pad Count: 2
footprint RESC0603X03L_C
pins: 1, 2

## R0201-10M
designator R?, comment 10M
Resistor, ±1%, 0.05W; Part Number: R0201-10M; Manufacturer: N.A.; Part number IPS: 00000001426; Note: Chip Res 1%; Pad Count: 2
footprint RESC0603X03L_C
pins: 1, 2

## R0201-12k
designator R?, comment 12k
Resistor, ±1%, 0.05W; Part Number: R0201-12k; Manufacturer: N.A.; Part number IPS: 00000007891; Note: Chip Res 1%; Pad Count: 2
footprint RESC0603X03L_C
pins: 1, 2

## R0201-18k
designator R?, comment 18k
Resistor, ±1%, 0.05W; Part Number: R0201-18k; Manufacturer: N.A.; Part number IPS: 00000001707; Note: Chip Res 1%; Pad Count: 2
footprint RESC0603X03L_C
pins: 1, 2

## R0201-33R
designator R?, comment 33R
Resistor, ±1%, 0.05W; Part Number: R0201-33R; Manufacturer: N.A.; Part number IPS: 00000003623; Note: Chip Res 1%; Pad Count: 2
footprint RESC0603X03L_C
pins: 1, 2

## R0201-47k
designator R?, comment 47k
Resistor, ±1%, 0.05W; Part Number: R0201-47k; Manufacturer: N.A.; Part number IPS: 00000001423; Note: Chip Res 1%; Pad Count: 2
footprint RESC0603X03L_C
pins: 1, 2

## R0201-100k
designator R?, comment 100k
Resistor, ±1%, 0.05W; Part Number: R0201-100k; Manufacturer: N.A.; Part number IPS: 00000001419; Note: Chip Res 1%; Pad Count: 2
footprint RESC0603X03L_C
pins: 1, 2

## R0201-120
designator R?, comment 120R
Resistor, ±1%, 0.05W; Part Number: R0201-120; Manufacturer: N.A.; Part number IPS: 00000000880; Note: Chip Res 1%; Pad Count: 2
footprint RESC0603X03L_C
pins: 1, 2

## R0201-120k
designator R?, comment 120k
Resistor, ±1%, 0.05W; Part Number: R0201-120k; Manufacturer: N.A.; Part number IPS: 00000001425; Note: Chip Res 1%; Pad Count: 2
footprint RESC0603X03L_C
pins: 1, 2

## R0201-150
designator R?, comment 150R
Resistor, ±1%, 0.05W; Part Number: R0201-150; Manufacturer: N.A.; Part number IPS: 00000001420; Note: Chip Res 1%; Pad Count: 2
footprint RESC0603X03L_C
pins: 1, 2

## R0201-150k
designator R?, comment 150k
Resistor, ±1%, 0.05W; Part Number: R0201-150k; Manufacturer: N.A.; Part number IPS: 00000001422; Note: Chip Res 1%; Pad Count: 2
footprint RESC0603X03L_C
pins: 1, 2

## R0201-330k
designator R?, comment 330k
Resistor, ±1%, 0.05W; Part Number: R0201-330k; Manufacturer: N.A.; Part number IPS: 00000001424; Note: Chip Res 1%; Pad Count: 2
footprint RESC0603X03L_C
pins: 1, 2

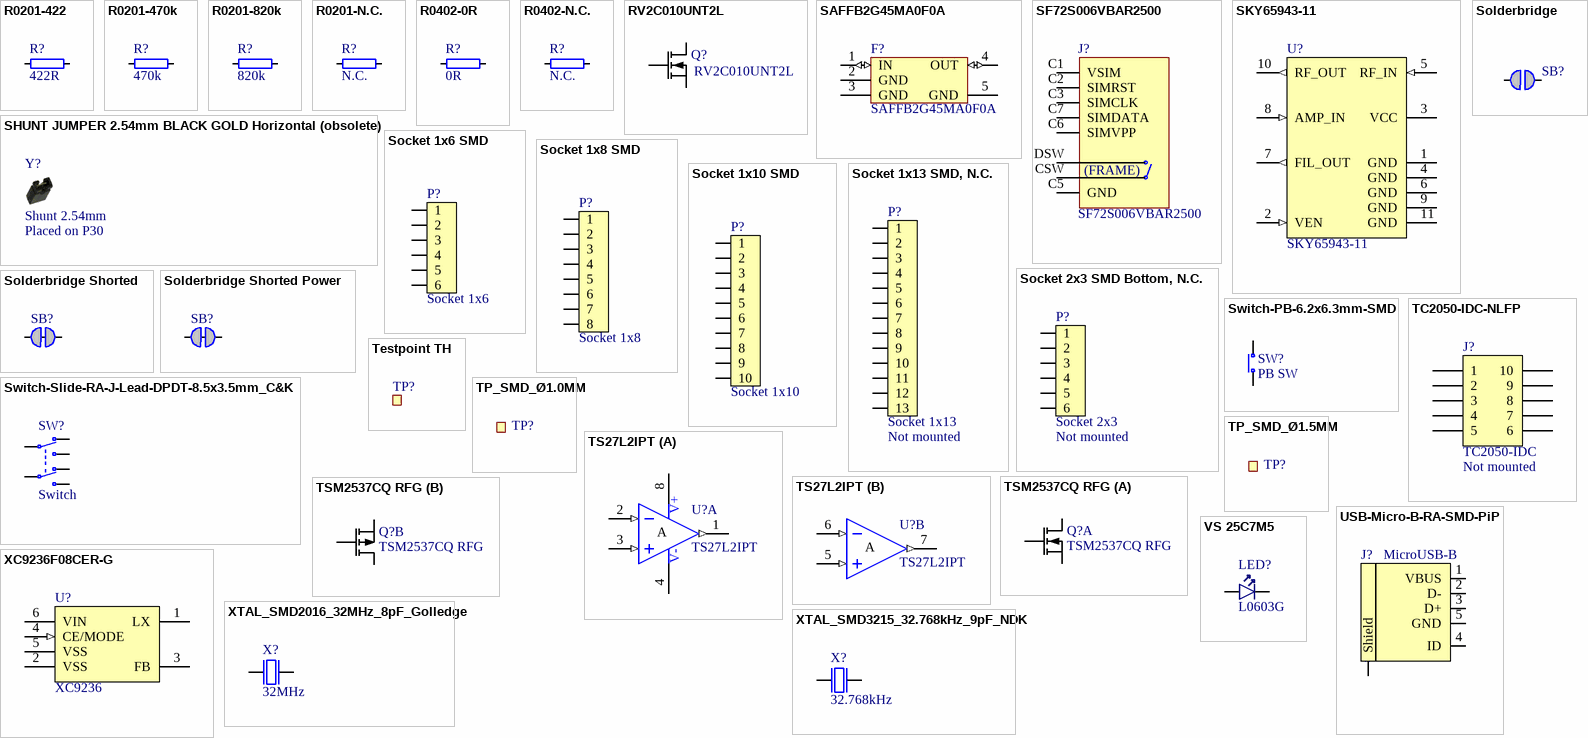
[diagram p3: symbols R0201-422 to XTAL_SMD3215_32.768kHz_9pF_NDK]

## R0201-422
designator R?, comment 422R
Resistor, ±1%, 0.05W; Part Number: R0201-422; Manufacturer: N.A.; Part number IPS: 00000002996; Note: Chip Res 1%; Pad Count: 2
footprint RESC0603X03L_C
pins: 1, 2

## R0201-470k
designator R?, comment 470k
Resistor, ±1%, 0.05W; Part Number: R0201-470k; Manufacturer: N.A.; Part number IPS: 00000001428; Note: Chip Res 1%; Pad Count: 2
footprint RESC0603X03L_C
pins: 1, 2

## R0201-820k
designator R?, comment 820k
Resistor, ±1%, 0.05W; Part Number: R0201-820k; Manufacturer: N.A.; Part number IPS: 00000001427; Note: Chip Res 1%; Pad Count: 2
footprint RESC0603X03L_C
pins: 1, 2

## R0201-N.C.
designator R?, comment N.C.
Not mounted; Part Number: R0201-N.C.; Manufacturer: N.A.; Note: Chip Res; Assembly: Not mounted; Pad Count: 2
footprint RESC0603X03L_C_NC
pins: 1, 2

## R0402-0R
designator R?, comment 0R
Resistor, ±5%, 0.063W; Part Number: R0402-0R; Manufacturer: N.A.; Part number IPS: 00000007128; Note: Chip Res 5%; Artikkelnr Noca: 27049000; Pad Count: 2
footprint RESC1005X04L
pins: 1, 2

## R0402-N.C.
designator R?, comment N.C.
Not mounted; Part Number: R0402-N.C.; Manufacturer: N.A.; Note: Chip Res; Assembly: Not mounted; Pad Count: 2
footprint RESC1005X04L_NC
pins: 1, 2

## RV2C010UNT2L
designator Q?
N-Channel MOSFET, 20V, 1A, 470mOhm, 400mW; Manufacturer: Rohm Semiconductor; Part number IPS: 00000009976; Note: N.A.; Artikkelnr Noca: 35010020; Pad Count: 3
footprint DFN65P100X40-3L
pins: 1 G, 2 S, 3 D

## SAFFB2G45MA0F0A
designator F?
2.4 GHz BPF; Manufacturer: Murata; Part number IPS: 00000001784, 80000001660; Artikkelnr Noca: N.A.; Pad Count: 5
footprint SAFFB2G45MA0F0A
pins: 1 IN (io), 2 GND (power), 3 GND (power), 4 OUT (io), 5 GND (power)

## SF72S006VBAR2500
designator J?
n 8 (6 + 2) Position Card Connector NANO SIM Surface Mount, Right Angle Gold; Manufacturer: JAE Electronics; Part number IPS: 00000009956; Note: N.A.; Pad Count: 8
footprint SF72S006VBAR2500
pins: 0 GND hidden to GND, C1 VSIM, C2 SIMRST, C3 SIMCLK, C5 GND, C6 SIMVPP, C7 SIMDATA, CSW, DSW

## SHUNT JUMPER 2.54mm BLACK GOLD Horizontal (obsolete)
designator Y?, comment Shunt 2.54mm  Assembly: Placed on P30
Shunt Jumper 2.54mm Black; Part Number: SHUNT JUMPER 2.54mm BLACK GOLD Horizontal (Obsolete); Manufacturer: N.A.; Part number IPS: 00000001916; Note: SHUNT JUMPER .1" BLACK GOLD, h=6.00mm, w=5.00mm; Artikkelnr Noca: 56099001; Pad Count: 2
footprint Shunt_2.54mm_Horizontal

## SKY65943-11
designator U?
GNSS Low-Noise Amplifier Front-End Module with Integrated Pre-Filter and Post-Filter; Manufacturer: Skyworks; Part number IPS: 00000002997; Note: N.A.; Pad Count: 10
footprint SKY65943-11
pins: 1 GND (power), 2 VEN (in), 3 VCC (power), 4 GND (power), 5 RF_IN (in), 6 GND (power), 7 FIL_OUT (out), 8 AMP_IN (in), 9 GND (power), 10 RF_OUT (out), 11 GND (power)

## Socket 1x6 SMD
designator P?, comment Socket 1x6
Socket 1x6, 2.54mm (100mil), SMD; Part Number: Socket 1x6 SMD; Manufacturer: W-CON; Manufacturer Part Number: 2171-106MS0CUNR1; Part number IPS: 00000009964; Note: N.A.; Artikkelnr Noca: 55030001; Pad Count: 6
footprint SOCKET_1x6_SMD
pins: 1, 2, 3, 4, 5, 6

## Socket 1x8 SMD
designator P?, comment Socket 1x8
Socket 1x8, 2.54mm (100mil), SMD; Part Number: Socket 1x8 SMD; Manufacturer: W-CON; Manufacturer Part Number: 2171-108MS0CUNR1; Part number IPS: 00000009963; Note: N.A.; Artikkelnr Noca: 55030002; Pad Count: 8
footprint SOCKET_1x8_SMD
pins: 1, 2, 3, 4, 5, 6, 7, 8

## Socket 1x10 SMD
designator P?, comment Socket 1x10
Socket 1x10, 2.54mm (100mil), SMD; Part Number: Socket 1x10 SMD; Manufacturer: W-CON; Manufacturer Part Number: 2171-110MS0CUNR1; Part number IPS: 00000009965; Note: N.A.; Artikkelnr Noca: 55030004; Pad Count: 10
footprint SOCKET_1x10_SMD
pins: 1, 2, 3, 4, 5, 6, 7, 8, 9, 10

## Socket 1x13 SMD, N.C.
designator P?, comment Socket 1x13  Assembly: Not mounted
Socket 1x13, 2.54mm (100mil), SMD; Part Number: Socket 1x13 SMD, N.C.; Manufacturer: W-CON; Manufacturer Part Number: 2171-113MS0CUNR1; Note: N.A.; Pad Count: 13
footprint LIST_1x13_SMD-NC
pins: 1, 2, 3, 4, 5, 6, 7, 8, 9, 10, 11, 12, 13

## Socket 2x3 SMD Bottom, N.C.
designator P?, comment Socket 2x3  Assembly: Not mounted
Socket 2x3, 2.54mm (100mil), SMD; Part Number: Socket 2x3 SMD Bottom, N.C.; Manufacturer: W-CON; Manufacturer Part Number: 2171-203MS0CUNR1; Note: N.A.; Artikkelnr Noca: 55030010; Pad Count: 6
footprint SOCKET_2x3_SMD-2.54mm-bottom-NC
pins: 1, 2, 3, 4, 5, 6

## Solderbridge
designator SB?  (value not drawn)  (no BOM)
Manufacturer: N.A.; Pad Count: 2
footprint Solderbridge
pins: 1 0, 2 1

## Solderbridge Shorted
designator SB?, comment Solderbridge  (value not drawn)  (net tie, no BOM)
Shorted Solderbridge; Part Number: Solderbridge Shorted; Manufacturer: N.A.; Pad Count: 2
footprint Solderbridge_Shorted
pins: 1 0, 2 1

## Solderbridge Shorted Power
designator SB?, comment Solderbridge  (value not drawn)  (net tie, no BOM)
Shorted Solderbridge Power; Part Number: Solderbridge Shorted Power; Manufacturer: N.A.; Pad Count: 2
footprint Solderbridge_Shorted_Power
pins: 1 0, 2 1

## Switch-PB-6.2x6.3mm-SMD
designator SW?, comment PB SW
Tactile Switch, SPNO, SMD, 160gf, 6.2x6.3x2.5mm; Part Number: Switch-PB-6.2x6.3mm-SMD; Manufacturer: Dailywell; Manufacturer Part Number: TS604VM1-025BR-R; Part number IPS: 00000007812; Note: N.A.; Artikkelnr Noca: 50019106; Pad Count: 4
footprint Switch-PB-6.2x6.3mm-SMD
pins: 1 N.O, 2 COM

## Switch-Slide-RA-J-Lead-DPDT-8.5x3.5mm_C&K
designator SW?, comment Switch
SMD slide Switch (ON-ON); Part Number: Switch-Slide-RA-J-Lead-DPDT-8.5x3.5mm_C&K; Manufacturer: C&K; Manufacturer Part Number: JS202011JAQN; Part number IPS: 00000007811; Note: N.A.; Pad Count: 6
footprint JS102011JAQN
pins: 1 N.O-1, 2 COM-1, 3 N.C-1, 4 N.O-2, 5 COM-2, 6 N.C-2

## TC2050-IDC-NLFP
designator J?, comment TC2050-IDC  Assembly: Not mounted  (no BOM)
CBL PLUG-OF-NAILS 10-PIN; Part Number: TC2050-IDC-NLFP; Manufacturer: Tag-Connect LLC; Artikkelnr Noca: N.A.; Pad Count: 10
footprint TC2050-IDC-NLFP
pins: 1, 2, 3, 4, 5, 6, 7, 8, 9, 10

## Testpoint TH
designator TP?, comment TP  (value not drawn)  (no BOM)
Testpoint, through hole; Part Number: Testpoint TH; Manufacturer: N.A.; Pad Count: 1
footprint TESTPAD-TH
pins: 1

## TP_SMD_Ø1.0MM
designator TP?, comment Ø1.0mm,SMD  (value not drawn)  (no BOM)
1.0mm circular SMD testpad; Part Number: TP_SMD_Ø1.0MM; Manufacturer: Nordic Semiconductor; Manufacturer Part Number: N.A.; Pad Count: 1
footprint TP_SMD_D1.0mm
pins: 1

## TP_SMD_Ø1.5MM
designator TP?, comment Ø1.5mm,SMD  (value not drawn)  (no BOM)
1.5mm circular SMD testpad; Part Number: TP_SMD_Ø1.5MM; Manufacturer: Nordic Semiconductor; Manufacturer Part Number: N.A.; Pad Count: 1
footprint TP_SMD_D1.5mm
pins: 1

## TS27L2IPT
designator U?
Precision very low power CMOS dual operational amplifier; Manufacturer: STMicroelectronics; Part number IPS: 00000009991; Note: N.A.; Artikkelnr Noca: 17010019; Pad Count: 8
footprint TSOP65P640X120-8N
part A pins: 1 OUT1 (out), 2 IN1- (in), 3 IN1+ (in), 4 V- (power), 8 V+ (power)
part B pins: 5 IN2+ (in), 6 IN2- (in), 7 OUT2 (out)

## TSM2537CQ RFG
designator Q?
Dual N & P Ch MOFET, 11.6A/9A, 90mOhm max, 6.25W; Manufacturer: Taiwan Semiconductor; Part number IPS: 00000001702; Note: N.A.; Pad Count: 6
footprint DFN65P200X200X80_HS-6N
part A pins: 1 S1, 2 G1, 6 D1
part B pins: 3 D2, 4 S2, 5 G2

## USB-Micro-B-RA-SMD-PiP
designator J?, comment MicroUSB-B
MicroUSB-B-SMT; Part Number: USB-Micro-B-RA-SMD-PiP; Manufacturer: Allen Creations Corp.; Manufacturer Part Number: AJU55-BS2111-L; Part number IPS: 00000007790; Note: N.A.; Artikkelnr Noca: 55029020; Pad Count: 5
footprint USB-Micro-B-RA-SMD-PiP
pins: 1 VBUS (power), 2 D-, 3 D+, 4 ID, 5 GND (power), 6 Shield (power)

## VS 25C7M5
designator LED?, comment L0603G
LED, Green, 0603, 573nm, Vf=2.0V, 24mcd, - 40 to +85°C; Part Number: VS 25C7M5; Manufacturer: Victory Electronics; Part number IPS: 00000001274, 00000009961; Note: N.A.; Artikkelnr Noca: 13019193; Pad Count: 2
footprint LED_0603_G
pins: 1 C, 2 A

## XC9236F08CER-G
designator U?, comment XC9236
600mA Driver Transistor Built-In, Synchronous Step-Down DC/DC Converters; Part Number: XC9236F08CER-G; Manufacturer: Torex Semiconductor; Part number IPS: 00000009989; Note: N.A.; Pad Count: 6
footprint USP-6C
pins: 1 LX, 2 VSS (power), 3 FB (power), 4 CE/MODE (in), 5 VSS (power), 6 VIN (power), 7 VSS (power) hidden to GND

## XTAL_SMD2016_32MHz_8pF_Golledge
designator X?, comment 32MHz
XTAL SMD 2016, 32MHz, Cl=8pF, Tol: ±10ppm, Stab: ±15ppm; Part Number: XTAL_SMD2016_32MHz_8pF_Golledge; Manufacturer: Golledge; Manufacturer Part Number: MP06003; Part number IPS: 00000001431; Part number Norautron: N.A.; Note: XTAL SMD 32.000MHz; Artikkelnr Noca: 22010050; Pad Count: 4
footprint BT-XTAL_2016
pins: 1 inp, 2 GND hidden to GND, 3 out, 4 GND hidden to GND

## XTAL_SMD3215_32.768kHz_9pF_NDK
designator X?, comment 32.768kHz
XTAL SMD 3215, 32.768kHz, 9pF, ±20ppm; Part Number: XTAL_SMD3215_32.768kHz_9pF_NDK; Manufacturer: NDK; Manufacturer Part Number: NX3215SA-32.768K-STD-MUA-9; Part number IPS: 00000005419; Part number Norautron: N.A.; Note: XTAL SMD 32.768kHz; Artikkelnr Noca: 22010049; Pad Count: 2
footprint XTAL_3215
pins: 1 inp, 2 out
